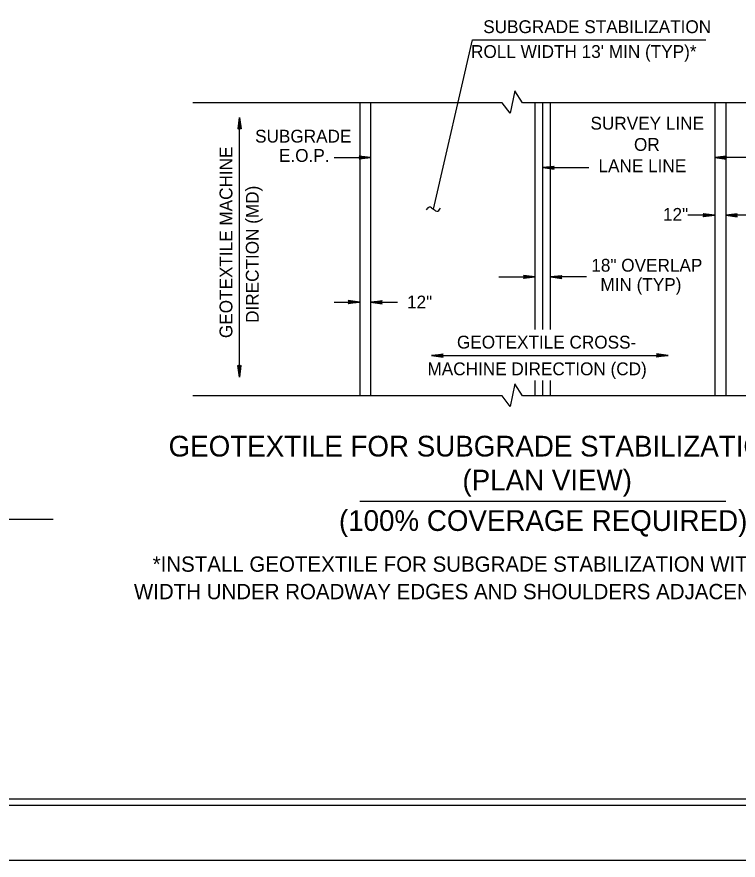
# Model space of a CAD drawing. Extents: x 1904401 to 1905163, y 193929 to 194736.
# Drawn here: x 1904910.6 to 1904969.4, y 194023.4 to 194092.2 of the extents above; entities that cross this region are included whole.
import ezdxf

# ---------------------------------------------------------------- set-up
doc = ezdxf.new("R2010")
doc.units = 0
for name, color, linetype in [('Old_Level_1', 7, 'Continuous'), ('Prop Dimension Text', 7, 'Continuous'), ('Sheet Cutting Line CELL', 7, 'Continuous'), ('Sheet Plot Border Inside CELL', 7, 'Continuous'), ('Sheet Plot Border Outside CELL', 7, 'Continuous'), ('Sheet Typical CELL', 7, 'Continuous')]:
    doc.layers.add(name, color=color, linetype=linetype)

msp = doc.modelspace()

# ---------------------------------------------------------------- linework, layer by layer
at = {"layer": 'Old_Level_1'}
msp.add_line((1904861.211, 194051.251), (1904913.604, 194051.251), dxfattribs=at)
at = {"layer": 'Prop Dimension Text'}
for p, q in [((1904944.592, 194076.512), (1904947.766, 194090.308)), ((1904947.766, 194090.308), (1904966.762, 194090.308)), ((1904938.569, 194085.19), (1904938.569, 194061.285)), ((1904939.462, 194085.19), (1904939.462, 194061.285)), ((1904952.858, 194066.702), (1904952.858, 194085.19)), ((1904953.482, 194066.702), (1904953.482, 194085.19)), ((1904954.106, 194066.702), (1904954.106, 194085.19)), ((1904967.502, 194085.19), (1904967.502, 194061.285)), ((1904968.394, 194085.19), (1904968.394, 194061.285)), ((1904928.774, 194084), (1904928.646, 194083.055)), ((1904928.664, 194083.072), (1904928.774, 194084)), ((1904928.774, 194084), (1904928.683, 194083.09)), ((1904928.701, 194083.107), (1904928.774, 194084)), ((1904928.774, 194084), (1904928.72, 194083.126)), ((1904928.737, 194083.142), (1904928.774, 194084)), ((1904928.774, 194084), (1904928.755, 194083.16)), ((1904928.774, 194084), (1904928.901, 194083.055)), ((1904928.774, 194083.177), (1904928.774, 194084)), ((1904928.792, 194083.16), (1904928.774, 194084)), ((1904928.774, 194084), (1904928.81, 194083.142)), ((1904928.828, 194083.126), (1904928.774, 194084)), ((1904928.774, 194084), (1904928.848, 194083.107)), ((1904928.866, 194083.09), (1904928.774, 194084)), ((1904928.774, 194084), (1904928.883, 194083.072)), ((1904928.774, 194062.829), (1904928.774, 194084)), ((1904928.646, 194083.055), (1904928.774, 194083.177)), ((1904928.774, 194083.177), (1904928.901, 194083.055)), ((1904936.492, 194080.719), (1904939.462, 194080.719)), ((1904939.462, 194080.719), (1904938.517, 194080.847)), ((1904938.517, 194080.847), (1904938.639, 194080.719)), ((1904939.462, 194080.719), (1904938.517, 194080.592)), ((1904938.639, 194080.719), (1904938.517, 194080.592)), ((1904938.534, 194080.829), (1904939.462, 194080.719)), ((1904939.462, 194080.719), (1904938.534, 194080.61)), ((1904939.462, 194080.719), (1904938.552, 194080.81)), ((1904938.552, 194080.627), (1904939.462, 194080.719)), ((1904938.569, 194080.792), (1904939.462, 194080.719)), ((1904939.462, 194080.719), (1904938.569, 194080.645)), ((1904939.462, 194080.719), (1904938.588, 194080.773)), ((1904938.588, 194080.665), (1904939.462, 194080.719)), ((1904938.603, 194080.756), (1904939.462, 194080.719)), ((1904939.462, 194080.719), (1904938.603, 194080.683)), ((1904939.462, 194080.719), (1904938.622, 194080.738)), ((1904938.622, 194080.701), (1904939.462, 194080.719)), ((1904938.639, 194080.719), (1904939.462, 194080.719)), ((1904967.502, 194080.719), (1904968.447, 194080.847)), ((1904968.43, 194080.829), (1904967.502, 194080.719)), ((1904967.502, 194080.719), (1904968.411, 194080.81)), ((1904968.394, 194080.792), (1904967.502, 194080.719)), ((1904967.502, 194080.719), (1904968.376, 194080.773)), ((1904968.36, 194080.756), (1904967.502, 194080.719)), ((1904967.502, 194080.719), (1904968.342, 194080.738)), ((1904970.472, 194080.719), (1904967.502, 194080.719)), ((1904967.502, 194080.719), (1904968.447, 194080.592)), ((1904968.325, 194080.719), (1904967.502, 194080.719)), ((1904968.342, 194080.701), (1904967.502, 194080.719)), ((1904967.502, 194080.719), (1904968.36, 194080.683)), ((1904968.376, 194080.665), (1904967.502, 194080.719)), ((1904967.502, 194080.719), (1904968.394, 194080.645)), ((1904968.411, 194080.627), (1904967.502, 194080.719)), ((1904967.502, 194080.719), (1904968.43, 194080.61)), ((1904968.447, 194080.847), (1904968.325, 194080.719)), ((1904968.325, 194080.719), (1904968.447, 194080.592)), ((1904953.482, 194079.899), (1904954.427, 194080.026)), ((1904953.482, 194079.899), (1904954.41, 194080.008)), ((1904954.391, 194079.991), (1904953.482, 194079.899)), ((1904953.482, 194079.899), (1904954.374, 194079.972)), ((1904954.356, 194079.953), (1904953.482, 194079.899)), ((1904953.482, 194079.899), (1904954.34, 194079.935)), ((1904954.322, 194079.917), (1904953.482, 194079.899)), ((1904953.482, 194079.899), (1904954.427, 194079.771)), ((1904954.41, 194079.789), (1904953.482, 194079.899)), ((1904953.482, 194079.899), (1904954.391, 194079.807)), ((1904954.374, 194079.826), (1904953.482, 194079.899)), ((1904953.482, 194079.899), (1904954.356, 194079.845)), ((1904954.34, 194079.862), (1904953.482, 194079.899)), ((1904953.482, 194079.899), (1904954.322, 194079.88)), ((1904954.305, 194079.899), (1904953.482, 194079.899)), ((1904953.482, 194079.899), (1904957.234, 194079.899)), ((1904954.305, 194079.899), (1904954.427, 194080.026)), ((1904954.427, 194079.771), (1904954.305, 194079.899)), ((1904944.017, 194076.456), (1904944.061, 194076.547)), ((1904944.426, 194076.63), (1904944.757, 194076.395)), ((1904945.076, 194076.475), (1904945.14, 194076.594)), ((1904967.502, 194076.015), (1904966.557, 194076.142)), ((1904966.679, 194076.015), (1904966.557, 194076.142)), ((1904967.502, 194076.015), (1904966.574, 194076.124)), ((1904966.593, 194076.107), (1904967.502, 194076.015)), ((1904967.502, 194076.015), (1904966.61, 194076.089)), ((1904968.394, 194076.015), (1904969.339, 194076.144)), ((1904969.322, 194076.125), (1904968.394, 194076.015)), ((1904968.394, 194076.015), (1904969.304, 194076.107)), ((1904969.287, 194076.089), (1904968.394, 194076.015)), ((1904969.339, 194076.144), (1904969.217, 194076.015)), ((1904967.502, 194076.015), (1904965.31, 194076.015)), ((1904967.502, 194076.015), (1904966.557, 194075.887)), ((1904966.557, 194075.887), (1904966.679, 194076.015)), ((1904966.574, 194075.906), (1904967.502, 194076.015)), ((1904967.502, 194076.015), (1904966.593, 194075.924)), ((1904966.61, 194075.942), (1904967.502, 194076.015)), ((1904966.628, 194076.069), (1904967.502, 194076.015)), ((1904967.502, 194076.015), (1904966.628, 194075.961)), ((1904967.502, 194076.015), (1904966.644, 194076.051)), ((1904966.644, 194075.978), (1904967.502, 194076.015)), ((1904966.662, 194076.033), (1904967.502, 194076.015)), ((1904967.502, 194076.015), (1904966.662, 194075.997)), ((1904966.679, 194076.015), (1904967.502, 194076.015)), ((1904968.394, 194076.015), (1904969.268, 194076.07)), ((1904969.252, 194076.053), (1904968.394, 194076.015)), ((1904968.394, 194076.015), (1904969.234, 194076.034)), ((1904970.472, 194076.015), (1904968.394, 194076.015)), ((1904968.394, 194076.015), (1904969.339, 194075.889)), ((1904969.217, 194076.015), (1904968.394, 194076.015)), ((1904969.234, 194075.998), (1904968.394, 194076.015)), ((1904968.394, 194076.015), (1904969.252, 194075.98)), ((1904969.268, 194075.961), (1904968.394, 194076.015)), ((1904968.394, 194076.015), (1904969.287, 194075.942)), ((1904969.304, 194075.924), (1904968.394, 194076.015)), ((1904968.394, 194076.015), (1904969.322, 194075.907)), ((1904969.217, 194076.015), (1904969.339, 194075.889)), ((1904949.91, 194070.987), (1904952.858, 194070.987)), ((1904952.858, 194070.987), (1904951.913, 194071.115)), ((1904951.913, 194071.115), (1904952.035, 194070.987)), ((1904952.858, 194070.987), (1904951.913, 194070.86)), ((1904952.035, 194070.987), (1904951.913, 194070.86)), ((1904951.93, 194071.097), (1904952.858, 194070.987)), ((1904952.858, 194070.987), (1904951.93, 194070.878)), ((1904952.858, 194070.987), (1904951.949, 194071.079)), ((1904951.949, 194070.895), (1904952.858, 194070.987)), ((1904951.966, 194071.06), (1904952.858, 194070.987)), ((1904952.858, 194070.987), (1904951.966, 194070.914)), ((1904952.858, 194070.987), (1904951.984, 194071.041)), ((1904951.984, 194070.933), (1904952.858, 194070.987)), ((1904952, 194071.024), (1904952.858, 194070.987)), ((1904952.858, 194070.987), (1904952, 194070.951)), ((1904952.858, 194070.987), (1904952.018, 194071.006)), ((1904952.018, 194070.969), (1904952.858, 194070.987)), ((1904952.035, 194070.987), (1904952.858, 194070.987)), ((1904954.106, 194070.987), (1904955.05, 194071.114)), ((1904954.106, 194070.987), (1904955.033, 194071.096)), ((1904955.015, 194071.079), (1904954.106, 194070.987)), ((1904954.106, 194070.987), (1904954.998, 194071.06)), ((1904954.98, 194071.041), (1904954.106, 194070.987)), ((1904954.106, 194070.987), (1904954.964, 194071.023)), ((1904954.946, 194071.005), (1904954.106, 194070.987)), ((1904954.106, 194070.987), (1904955.05, 194070.859)), ((1904955.033, 194070.877), (1904954.106, 194070.987)), ((1904954.106, 194070.987), (1904955.015, 194070.895)), ((1904954.998, 194070.913), (1904954.106, 194070.987)), ((1904954.106, 194070.987), (1904954.98, 194070.933)), ((1904954.964, 194070.95), (1904954.106, 194070.987)), ((1904954.106, 194070.987), (1904954.946, 194070.968)), ((1904954.929, 194070.987), (1904954.106, 194070.987)), ((1904957.053, 194070.987), (1904954.106, 194070.987)), ((1904954.929, 194070.987), (1904955.05, 194071.114)), ((1904955.05, 194070.859), (1904954.929, 194070.987)), ((1904936.492, 194068.936), (1904938.569, 194068.936)), ((1904938.569, 194068.936), (1904937.625, 194069.064)), ((1904937.625, 194069.064), (1904937.746, 194068.936)), ((1904938.569, 194068.936), (1904937.625, 194068.809)), ((1904937.746, 194068.936), (1904937.625, 194068.809)), ((1904937.642, 194069.046), (1904938.569, 194068.936)), ((1904938.569, 194068.936), (1904937.642, 194068.827)), ((1904938.569, 194068.936), (1904937.66, 194069.028)), ((1904937.66, 194068.844), (1904938.569, 194068.936)), ((1904937.677, 194069.01), (1904938.569, 194068.936)), ((1904938.569, 194068.936), (1904937.677, 194068.863)), ((1904938.569, 194068.936), (1904937.695, 194068.99)), ((1904937.695, 194068.882), (1904938.569, 194068.936)), ((1904937.711, 194068.973), (1904938.569, 194068.936)), ((1904938.569, 194068.936), (1904937.711, 194068.9)), ((1904938.569, 194068.936), (1904937.729, 194068.955)), ((1904937.729, 194068.919), (1904938.569, 194068.936)), ((1904937.746, 194068.936), (1904938.569, 194068.936)), ((1904939.462, 194068.936), (1904940.406, 194069.063)), ((1904939.462, 194068.936), (1904940.389, 194069.045)), ((1904940.371, 194069.028), (1904939.462, 194068.936)), ((1904939.462, 194068.936), (1904940.354, 194069.009)), ((1904940.336, 194068.99), (1904939.462, 194068.936)), ((1904939.462, 194068.936), (1904940.32, 194068.972)), ((1904940.302, 194068.954), (1904939.462, 194068.936)), ((1904939.462, 194068.936), (1904941.654, 194068.936)), ((1904939.462, 194068.936), (1904940.406, 194068.808)), ((1904940.389, 194068.826), (1904939.462, 194068.936)), ((1904939.462, 194068.936), (1904940.371, 194068.844)), ((1904940.354, 194068.863), (1904939.462, 194068.936)), ((1904939.462, 194068.936), (1904940.336, 194068.882)), ((1904940.32, 194068.899), (1904939.462, 194068.936)), ((1904939.462, 194068.936), (1904940.302, 194068.917)), ((1904940.285, 194068.936), (1904939.462, 194068.936)), ((1904940.285, 194068.936), (1904940.406, 194069.063)), ((1904940.406, 194068.808), (1904940.285, 194068.936)), ((1904944.429, 194064.587), (1904945.374, 194064.713)), ((1904944.429, 194064.587), (1904945.357, 194064.695)), ((1904945.338, 194064.678), (1904944.429, 194064.587)), ((1904944.429, 194064.587), (1904945.321, 194064.66)), ((1904945.303, 194064.641), (1904944.429, 194064.587)), ((1904944.429, 194064.587), (1904945.287, 194064.622)), ((1904945.269, 194064.604), (1904944.429, 194064.587)), ((1904944.429, 194064.587), (1904945.374, 194064.458)), ((1904945.357, 194064.477), (1904944.429, 194064.587)), ((1904944.429, 194064.587), (1904945.338, 194064.495)), ((1904945.321, 194064.513), (1904944.429, 194064.587)), ((1904944.429, 194064.587), (1904945.303, 194064.532)), ((1904945.287, 194064.55), (1904944.429, 194064.587)), ((1904944.429, 194064.587), (1904945.269, 194064.568)), ((1904945.252, 194064.587), (1904944.429, 194064.587)), ((1904944.429, 194064.587), (1904963.701, 194064.587)), ((1904945.252, 194064.587), (1904945.374, 194064.713)), ((1904945.374, 194064.458), (1904945.252, 194064.587)), ((1904963.701, 194064.585), (1904962.756, 194064.713)), ((1904962.756, 194064.713), (1904962.878, 194064.585)), ((1904963.701, 194064.585), (1904962.756, 194064.458)), ((1904962.878, 194064.585), (1904962.756, 194064.458)), ((1904962.773, 194064.695), (1904963.701, 194064.585)), ((1904963.701, 194064.585), (1904962.773, 194064.477)), ((1904963.701, 194064.585), (1904962.791, 194064.677)), ((1904962.791, 194064.494), (1904963.701, 194064.585)), ((1904962.808, 194064.659), (1904963.701, 194064.585)), ((1904963.701, 194064.585), (1904962.808, 194064.512)), ((1904963.701, 194064.585), (1904962.826, 194064.639)), ((1904962.826, 194064.531), (1904963.701, 194064.585)), ((1904962.842, 194064.622), (1904963.701, 194064.585)), ((1904963.701, 194064.585), (1904962.842, 194064.55)), ((1904963.701, 194064.585), (1904962.861, 194064.604)), ((1904962.861, 194064.568), (1904963.701, 194064.585)), ((1904962.878, 194064.585), (1904963.701, 194064.585)), ((1904928.774, 194062.829), (1904928.647, 194063.774)), ((1904928.774, 194063.652), (1904928.647, 194063.774)), ((1904928.774, 194062.829), (1904928.666, 194063.757)), ((1904928.683, 194063.739), (1904928.774, 194062.829)), ((1904928.774, 194062.829), (1904928.701, 194063.722)), ((1904928.774, 194062.829), (1904928.902, 194063.774)), ((1904928.902, 194063.774), (1904928.774, 194063.652)), ((1904928.884, 194063.757), (1904928.774, 194062.829)), ((1904928.774, 194062.829), (1904928.866, 194063.739)), ((1904928.848, 194063.722), (1904928.774, 194062.829)), ((1904928.72, 194063.703), (1904928.774, 194062.829)), ((1904928.774, 194062.829), (1904928.739, 194063.687)), ((1904928.757, 194063.669), (1904928.774, 194062.829)), ((1904928.774, 194062.829), (1904928.828, 194063.703)), ((1904928.811, 194063.687), (1904928.774, 194062.829)), ((1904928.774, 194062.829), (1904928.793, 194063.669)), ((1904928.774, 194063.652), (1904928.774, 194062.829)), ((1904952.858, 194061.285), (1904952.858, 194062.554)), ((1904953.482, 194061.285), (1904953.482, 194062.554)), ((1904954.106, 194061.285), (1904954.106, 194062.554)), ((1904938.569, 194052.7), (1904968.394, 194052.7))]:
    msp.add_line(p, q, dxfattribs=at)
for points in [[(1904979.442, 194085.19), (1904951.83, 194085.19), (1904951.213, 194086.169), (1904950.82, 194084.344), (1904950.182, 194085.19), (1904924.974, 194085.19)], [(1904979.442, 194061.285), (1904951.83, 194061.285), (1904951.213, 194062.264), (1904950.82, 194060.439), (1904950.182, 194061.285), (1904924.974, 194061.285)]]:
    msp.add_lwpolyline(points, dxfattribs=at)
for centre, radius, start, end in [((1904944.274, 194076.46), 0.228, 48.03212, 157.83099), ((1904944.886, 194076.549), 0.203, 230.47697, 338.76255)]:
    msp.add_arc(centre, radius, start, end, dxfattribs=at)
at = {"layer": 'Sheet Cutting Line CELL'}
msp.add_line((1904710.692, 194023.443), (1905047.492, 194023.443), dxfattribs=at)
at = {"layer": 'Sheet Plot Border Inside CELL'}
msp.add_lwpolyline([(1905046.592, 194238.953), (1904713.292, 194238.953), (1904713.292, 194027.933), (1905046.592, 194027.933)], close=True, dxfattribs=at)
at = {"layer": 'Sheet Plot Border Outside CELL'}
msp.add_lwpolyline([(1905047.492, 194243.443), (1904710.692, 194243.443), (1904710.692, 194023.443), (1905047.492, 194023.443)], close=True, dxfattribs=at)
at = {"layer": 'Sheet Typical CELL'}
msp.add_lwpolyline([(1905044.092, 194238.443), (1904744.092, 194238.443), (1904744.092, 194028.443), (1905044.092, 194028.443)], close=True, dxfattribs=at)

# ---------------------------------------------------------------- texts
at = {"layer": 'Prop Dimension Text'}
for s, height, p in [('SUBGRADE STABILIZATION', 1.04588, (1904948.634, 194090.868)), ("ROLL WIDTH 13' MIN (TYP)*", 1.04588, (1904947.642, 194088.844)), ('SURVEY LINE', 1.04588, (1904957.376, 194083.001)), ('SUBGRADE', 1.0459, (1904930.045, 194081.944)), ('OR', 1.0459, (1904960.919, 194081.269)), ('E.O.P.', 1.0459, (1904931.993, 194080.372)), ('LANE LINE', 1.0459, (1904958.027, 194079.527)), ('12"', 1.0459, (1904963.281, 194075.566)), ('18" OVERLAP', 1.04588, (1904957.441, 194071.42)), ('MIN (TYP)', 1.0459, (1904958.182, 194069.848)), ('12"', 1.0459, (1904942.424, 194068.421)), ('GEOTEXTILE CROSS-', 1.04588, (1904946.493, 194065.152)), ('MACHINE DIRECTION (CD)', 1.04588, (1904944.091, 194062.975)), ('GEOTEXTILE FOR SUBGRADE STABILIZATION PLACEMENT', 1.68995, (1904922.999, 194056.35)), ('(PLAN VIEW)', 1.68995, (1904946.942, 194053.581)), ('(100% COVERAGE REQUIRED)', 1.68995, (1904936.879, 194050.284)), ('*INSTALL GEOTEXTILE FOR SUBGRADE STABILIZATION WITH MINIMUM ROLL', 1.24777, (1904921.7, 194046.954)), ('WIDTH UNDER ROADWAY EDGES AND SHOULDERS ADJACENT TO FILL SLOPES', 1.24777, (1904920.17, 194044.716))]:
    msp.add_text(s, height=height, dxfattribs=at).set_placement(p)
for s, p in [('GEOTEXTILE MACHINE', (1904928.197, 194066.004)), ('DIRECTION (MD)', (1904930.338, 194067.243))]:
    msp.add_text(s, height=1.04588, rotation=90, dxfattribs=at).set_placement(p)

doc.saveas('drawing.dxf')
